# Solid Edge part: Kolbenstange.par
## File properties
Username: ahadarics
Dokumentum tartalom típus: 0
Author: ahadarics
Last saved by: ahadarics
Revision: 89
Sűrűség: 0,000 kg/m^3
Pontosság: 0,990
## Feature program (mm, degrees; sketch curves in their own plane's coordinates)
base feature "unnamed BaseFeature 1"
sketch for "unnamed Protrusion 1" plane through (59.95, 0, 0) normal (1, 0, 0) x-axis (0, -1, 0)
  circle centre (0, 0) radius 10
extrude "unnamed Protrusion 1" add finite 32 along -normal
thread "Menet_1"  ThreadDepth = 20 mm
chamfer "Letörés_1" setback 0.7
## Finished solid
Body 1: solid body, 13 faces, 23 edges, 12 vertices.
  Faces by surface: plane 9, cylinder 3, cone 1
  Edges by curve: line 12, circle 11
Bounding box of the edges (mm): 593.500 x 20.000 x 20.000, from (-533.55, -10, -10) to (59.95, 10, 10).
Cylindrical faces by radius (mm): R4 x2, R10 x1
Conical faces (half-angle, radius in mm at the cone's reference point): 45 deg R3.3 x1
Planar faces by outward normal: +x 3, +z 1, -x 4, -z 1
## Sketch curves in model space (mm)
circle centre (59.95, 0, 0) radius 10
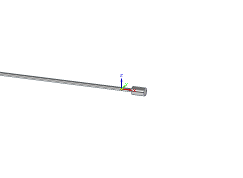
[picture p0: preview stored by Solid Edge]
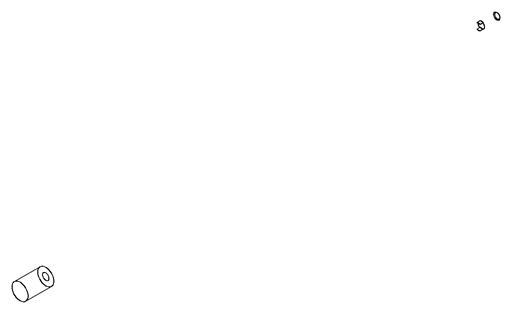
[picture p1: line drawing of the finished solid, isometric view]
